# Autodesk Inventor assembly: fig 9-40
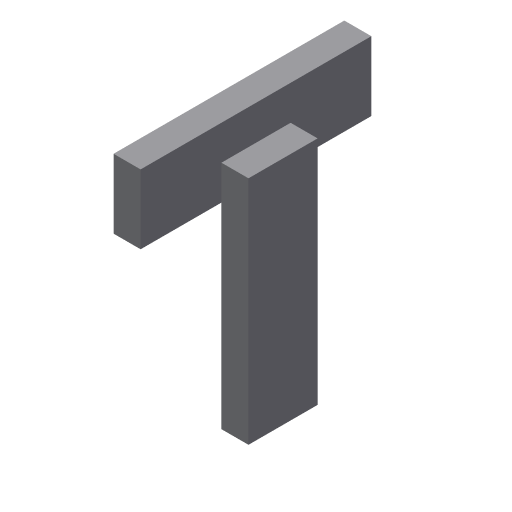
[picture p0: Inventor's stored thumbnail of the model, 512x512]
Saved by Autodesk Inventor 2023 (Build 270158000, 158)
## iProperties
Created: 2013-07
Part Number: fig 9-40
Document SubType Name: Assembly
Designer: CADCIM
Author: CADCIM
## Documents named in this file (2)
- D:\PROJECTS\Project 2022\Autodesk Inventor For Professional 2023\RESOURCES INVENTOR 2023\RESOURCES INVENTOR 2023\Inventor_2023_Part\Inventor_2023_Part\c09_Inv_2023_prt\fig 9-41.iam
- D:\PROJECTS\Project 2022\Autodesk Inventor For Professional 2023\RESOURCES INVENTOR 2023\RESOURCES INVENTOR 2023\Inventor_2023_Part\Inventor_2023_Part\c09_Inv_2023_prt\12.ipt
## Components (2 placed, 1 different names)
1. 12:1 — Rigid:1
2. 12:2 — Rigid:1
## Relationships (1: WeldJoint 1)
- Rigid:1 [WeldJoint]: 12:1 ↔ 12:2
